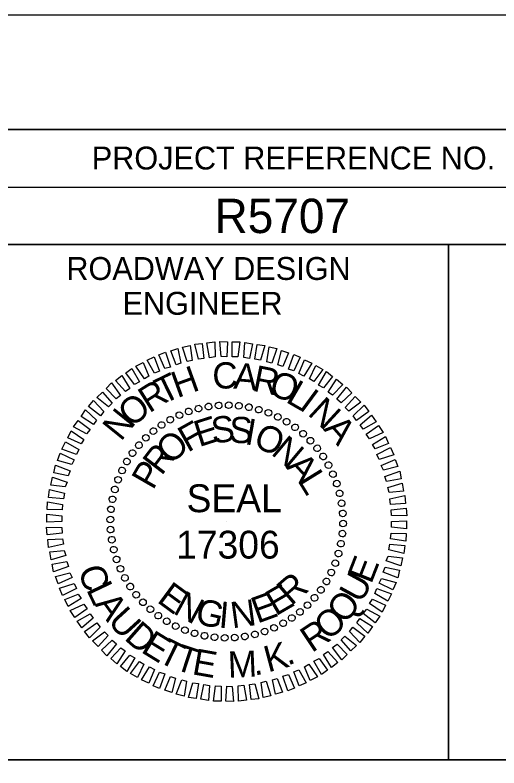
# Model space of a CAD drawing. Extents: x 573058.4 to 573116.8, y -55221.3 to -55199.3.
# Drawn here: x 573107.622 to 573109.734, y -55202.584 to -55199.298 of the extents above; entities that cross this region are included whole.
import ezdxf

# ---------------------------------------------------------------- set-up
doc = ezdxf.new("R2010")
doc.units = 0
for name, color, linetype in [('Prop Dimension', 7, 'Continuous'), ('Scratch_Level_1', 7, 'Continuous'), ('Sheet Data Field CELL', 7, 'Continuous'), ('Sheet Plot Border Inside CELL', 7, 'Continuous'), ('Sheet Profile CELL', 7, 'Continuous'), ('Sheet Sticker Exception Certification CELL', 7, 'Continuous')]:
    doc.layers.add(name, color=color, linetype=linetype)

msp = doc.modelspace()

# ---------------------------------------------------------------- linework, layer by layer
at = {"layer": 'Prop Dimension'}
for p, q in [((573108.4225, -55201.0155), (573108.4225, -55201.0155)), ((573108.467, -55201.0074), (573108.467, -55201.0074)), ((573108.5105, -55201.0013), (573108.5105, -55201.0013)), ((573108.555, -55201.0004), (573108.555, -55201.0004)), ((573108.5996, -55201.0034), (573108.5996, -55201.0034)), ((573108.6432, -55201.0106), (573108.6432, -55201.0106)), ((573108.6857, -55201.0196), (573108.6857, -55201.0196)), ((573108.3395, -55201.0439), (573108.3395, -55201.0439)), ((573108.38, -55201.0277), (573108.38, -55201.0277)), ((573108.7283, -55201.0337), (573108.7283, -55201.0337)), ((573108.7688, -55201.052), (573108.7688, -55201.052)), ((573108.2614, -55201.0875), (573108.2614, -55201.0875)), ((573108.2999, -55201.0641), (573108.2999, -55201.0641)), ((573108.8081, -55201.0722), (573108.8081, -55201.0722)), ((573108.2261, -55201.1127), (573108.2261, -55201.1127)), ((573108.8446, -55201.0976), (573108.8446, -55201.0976)), ((573108.8801, -55201.1249), (573108.8801, -55201.1249)), ((573108.1925, -55201.1431), (573108.1925, -55201.1431)), ((573108.9114, -55201.1552), (573108.9114, -55201.1552)), ((573108.1622, -55201.1746), (573108.1622, -55201.1746)), ((573108.9418, -55201.1888), (573108.9418, -55201.1888)), ((573108.1349, -55201.2099), (573108.1349, -55201.2099)), ((573108.1095, -55201.2464), (573108.1095, -55201.2464)), ((573108.9672, -55201.2241), (573108.9672, -55201.2241)), ((573108.0893, -55201.286), (573108.0893, -55201.286)), ((573108.9904, -55201.2626), (573108.9904, -55201.2626)), ((573109.0106, -55201.3022), (573109.0106, -55201.3022)), ((573108.071, -55201.3265), (573108.071, -55201.3265)), ((573109.0268, -55201.3427), (573109.0268, -55201.3427)), ((573108.0569, -55201.369), (573108.0569, -55201.369)), ((573109.039, -55201.3852), (573109.039, -55201.3852)), ((573108.0479, -55201.4115), (573108.0479, -55201.4115)), ((573109.0471, -55201.4297), (573109.0471, -55201.4297)), ((573108.0407, -55201.4549), (573108.0407, -55201.4549)), ((573109.0532, -55201.4732), (573109.0532, -55201.4732)), ((573108.0377, -55201.4995), (573108.0377, -55201.4995)), ((573108.546, -55201.5087), (573108.546, -55201.5087)), ((573109.0543, -55201.5177), (573109.0543, -55201.5177)), ((573108.0386, -55201.544), (573108.0386, -55201.544)), ((573109.0511, -55201.5623), (573109.0511, -55201.5623)), ((573108.0447, -55201.5877), (573108.0447, -55201.5877)), ((573109.0442, -55201.6059), (573109.0442, -55201.6059)), ((573108.0528, -55201.6322), (573108.0528, -55201.6322)), ((573109.0349, -55201.6484), (573109.0349, -55201.6484)), ((573108.065, -55201.6748), (573108.065, -55201.6748)), ((573108.0812, -55201.7153), (573108.0812, -55201.7153)), ((573109.0208, -55201.691), (573109.0208, -55201.691)), ((573109.0025, -55201.7315), (573109.0025, -55201.7315)), ((573108.1014, -55201.7546), (573108.1014, -55201.7546)), ((573108.9823, -55201.7708), (573108.9823, -55201.7708)), ((573108.1248, -55201.7931), (573108.1248, -55201.7931)), ((573108.9571, -55201.8073), (573108.9571, -55201.8073)), ((573108.15, -55201.8287), (573108.15, -55201.8287)), ((573108.9296, -55201.8428), (573108.9296, -55201.8428)), ((573108.1804, -55201.862), (573108.1804, -55201.862)), ((573108.8993, -55201.8741), (573108.8993, -55201.8741)), ((573108.2119, -55201.8923), (573108.2119, -55201.8923)), ((573108.866, -55201.9045), (573108.866, -55201.9045)), ((573108.2472, -55201.9198), (573108.2472, -55201.9198)), ((573108.2837, -55201.945), (573108.2837, -55201.945)), ((573108.8304, -55201.9299), (573108.8304, -55201.9299)), ((573108.3233, -55201.9652), (573108.3233, -55201.9652)), ((573108.7526, -55201.9733), (573108.7526, -55201.9733)), ((573108.7919, -55201.9531), (573108.7919, -55201.9531)), ((573108.3638, -55201.9835), (573108.3638, -55201.9835)), ((573108.4063, -55201.9976), (573108.4063, -55201.9976)), ((573108.4488, -55202.0069), (573108.4488, -55202.0069)), ((573108.625, -55202.0098), (573108.625, -55202.0098)), ((573108.6695, -55202.0017), (573108.6695, -55202.0017)), ((573108.7121, -55201.9895), (573108.7121, -55201.9895)), ((573108.4922, -55202.0138), (573108.4922, -55202.0138)), ((573108.5368, -55202.017), (573108.5368, -55202.017)), ((573108.5813, -55202.0159), (573108.5813, -55202.0159))]:
    msp.add_line(p, q, dxfattribs=at)
for points in [[(573108.4711, -55200.7939), (573108.4598, -55200.7291), (573108.4943, -55200.725), (573108.4954, -55200.7907)], [(573108.5217, -55200.7887), (573108.5165, -55200.723), (573108.5501, -55200.7239), (573108.546, -55200.7898)], [(573108.5703, -55200.7898), (573108.5703, -55200.7239), (573108.6036, -55200.725), (573108.5946, -55200.7907)], [(573108.6209, -55200.7928), (573108.625, -55200.7271), (573108.6583, -55200.7331), (573108.6452, -55200.7968)], [(573108.3253, -55200.8243), (573108.3019, -55200.7635), (573108.3334, -55200.7543), (573108.3464, -55200.8171)], [(573108.3739, -55200.811), (573108.3525, -55200.7473), (573108.3869, -55200.7401), (573108.395, -55200.806)], [(573108.4225, -55200.8), (573108.4063, -55200.7352), (573108.4396, -55200.732), (573108.4468, -55200.7968)], [(573108.6695, -55200.8009), (573108.6785, -55200.7361), (573108.7121, -55200.7412), (573108.6938, -55200.804)], [(573108.7211, -55200.8121), (573108.7312, -55200.7462), (573108.7656, -55200.7543), (573108.7424, -55200.8171)], [(573108.7697, -55200.8252), (573108.785, -55200.7624), (573108.8162, -55200.7725), (573108.791, -55200.8324)], [(573108.231, -55200.8616), (573108.1986, -55200.8049), (573108.2301, -55200.7907), (573108.2533, -55200.8526)], [(573108.2756, -55200.8405), (573108.2492, -55200.7817), (573108.2796, -55200.7696), (573108.301, -55200.8344)], [(573108.8153, -55200.8434), (573108.8385, -55200.7797), (573108.8669, -55200.7919), (573108.8385, -55200.8506)], [(573108.1876, -55200.8859), (573108.15, -55200.8312), (573108.1815, -55200.815), (573108.2067, -55200.8738)], [(573108.8608, -55200.8627), (573108.8862, -55200.8029), (573108.9175, -55200.8171), (573108.8831, -55200.8738)], [(573108.9074, -55200.8859), (573108.9348, -55200.8283), (573108.9652, -55200.8454), (573108.9267, -55200.8981)], [(573108.143, -55200.9113), (573108.1055, -55200.8596), (573108.1318, -55200.8405), (573108.1653, -55200.8992)], [(573108.947, -55200.9134), (573108.9823, -55200.8546), (573109.0086, -55200.8758), (573108.9692, -55200.9255)], [(573108.1046, -55200.9417), (573108.0609, -55200.8931), (573108.0884, -55200.8717), (573108.1237, -55200.9284)], [(573108.9884, -55200.9437), (573109.0259, -55200.8879), (573109.0523, -55200.9102), (573109.0077, -55200.9579)], [(573108.0641, -55200.973), (573108.0195, -55200.9284), (573108.0438, -55200.9041), (573108.0832, -55200.9588)], [(573109.0268, -55200.975), (573109.0685, -55200.9224), (573109.0928, -55200.9467), (573109.0462, -55200.9903)], [(573108.0305, -55201.0085), (573107.979, -55200.9669), (573108.0042, -55200.9437), (573108.0467, -55200.9923)], [(573107.9952, -55201.047), (573107.9426, -55201.0074), (573107.9648, -55200.9811), (573108.0094, -55201.0288)], [(573109.0633, -55201.0106), (573109.1069, -55200.9629), (573109.1312, -55200.9872), (573109.0786, -55201.0268)], [(573107.9648, -55201.0855), (573107.9102, -55201.0511), (573107.9293, -55201.0216), (573107.9779, -55201.0661)], [(573109.0988, -55201.047), (573109.1454, -55201.0013), (573109.1666, -55201.0288), (573109.113, -55201.0673)], [(573109.1292, -55201.0864), (573109.1787, -55201.0439), (573109.1981, -55201.0733), (573109.1414, -55201.1057)], [(573107.9345, -55201.126), (573107.8778, -55201.0956), (573107.898, -55201.0673), (573107.9507, -55201.1078)], [(573109.1555, -55201.128), (573109.2091, -55201.0895), (573109.2284, -55201.1199), (573109.1697, -55201.1483)], [(573107.9102, -55201.1694), (573107.8523, -55201.1442), (573107.8676, -55201.1127), (573107.9223, -55201.1503)], [(573109.1819, -55201.1726), (573109.2386, -55201.137), (573109.2516, -55201.1685), (573109.194, -55201.1917)], [(573107.8899, -55201.216), (573107.8271, -55201.1928), (573107.8422, -55201.1613), (573107.9, -55201.1937)], [(573109.2021, -55201.216), (573109.2617, -55201.1856), (573109.275, -55201.218), (573109.2122, -55201.2383)], [(573107.8697, -55201.2605), (573107.8069, -55201.2423), (573107.8199, -55201.211), (573107.8807, -55201.2394)], [(573109.2203, -55201.2637), (573109.282, -55201.2374), (573109.2932, -55201.2686), (573109.2305, -55201.2848)], [(573107.8544, -55201.3091), (573107.7916, -55201.2961), (573107.7988, -55201.2626), (573107.8625, -55201.288)], [(573109.2365, -55201.3123), (573109.3013, -55201.2889), (573109.3074, -55201.3224), (573109.2435, -55201.3334)], [(573107.8413, -55201.3577), (573107.7785, -55201.3496), (573107.7855, -55201.3152), (573107.8494, -55201.3366)], [(573109.2487, -55201.3609), (573109.3124, -55201.3415), (573109.3184, -55201.376), (573109.2548, -55201.382)], [(573107.8332, -55201.4095), (573107.7684, -55201.4034), (573107.7725, -55201.369), (573107.8382, -55201.3852)], [(573109.2577, -55201.4095), (573109.3236, -55201.3953), (573109.3265, -55201.4297), (573109.2617, -55201.4338)], [(573107.828, -55201.4581), (573107.7623, -55201.4561), (573107.7644, -55201.4225), (573107.8301, -55201.4338)], [(573109.2638, -55201.4581), (573109.3297, -55201.45), (573109.3317, -55201.4844), (573109.2658, -55201.4824)], [(573107.8271, -55201.5087), (573107.7612, -55201.5116), (573107.7612, -55201.4772), (573107.8271, -55201.4844)], [(573109.2649, -55201.5087), (573109.3306, -55201.5056), (573109.3306, -55201.54), (573109.2649, -55201.533)], [(573107.828, -55201.5593), (573107.7623, -55201.5674), (573107.7603, -55201.533), (573107.826, -55201.535)], [(573107.8341, -55201.6079), (573107.7684, -55201.6221), (573107.7653, -55201.5877), (573107.8301, -55201.5836)], [(573109.2638, -55201.5593), (573109.3297, -55201.5614), (573109.3277, -55201.5947), (573109.2617, -55201.5836)], [(573109.2588, -55201.6079), (573109.3236, -55201.614), (573109.3196, -55201.6484), (573109.2536, -55201.6322)], [(573107.8433, -55201.6565), (573107.7794, -55201.6757), (573107.7734, -55201.6412), (573107.8373, -55201.6352)], [(573109.2507, -55201.6595), (573109.3135, -55201.6676), (573109.3063, -55201.702), (573109.2426, -55201.6808)], [(573107.8555, -55201.7051), (573107.7907, -55201.7283), (573107.7846, -55201.695), (573107.8483, -55201.6838)], [(573109.2374, -55201.7081), (573109.3002, -55201.7213), (573109.2932, -55201.7546), (573109.2293, -55201.7294)], [(573107.8717, -55201.7537), (573107.8098, -55201.7801), (573107.7988, -55201.7486), (573107.8616, -55201.7324)], [(573107.8899, -55201.8012), (573107.8301, -55201.8316), (573107.817, -55201.7992), (573107.8798, -55201.7789)], [(573109.2224, -55201.7567), (573109.2851, -55201.7749), (573109.2719, -55201.8064), (573109.2111, -55201.778)], [(573109.2021, -55201.8012), (573109.2649, -55201.8246), (573109.2496, -55201.8559), (573109.192, -55201.8235)], [(573107.9102, -55201.8449), (573107.8535, -55201.8802), (573107.8402, -55201.8489), (573107.898, -55201.8255)], [(573109.1819, -55201.8478), (573109.2395, -55201.8732), (573109.2244, -55201.9045), (573109.1697, -55201.8671)], [(573107.9365, -55201.8894), (573107.8827, -55201.9279), (573107.8636, -55201.8975), (573107.9223, -55201.8692)], [(573107.9628, -55201.9308), (573107.9131, -55201.9733), (573107.894, -55201.9441), (573107.9507, -55201.9117)], [(573109.1576, -55201.8914), (573109.2143, -55201.9218), (573109.194, -55201.9502), (573109.1414, -55201.9097)], [(573109.1272, -55201.9319), (573109.1819, -55201.9664), (573109.1625, -55201.9956), (573109.1139, -55201.9511)], [(573107.9932, -55201.9704), (573107.9466, -55202.0159), (573107.9252, -55201.9886), (573107.979, -55201.9502)], [(573109.0968, -55201.9704), (573109.1495, -55202.0098), (573109.1272, -55202.0361), (573109.0826, -55201.9886)], [(573108.0285, -55202.0069), (573107.9851, -55202.0543), (573107.9608, -55202.03), (573108.0134, -55201.9907)], [(573109.0613, -55202.0089), (573109.113, -55202.0503), (573109.0876, -55202.0737), (573109.0451, -55202.0251)], [(573108.065, -55202.0422), (573108.0236, -55202.0948), (573107.9993, -55202.0705), (573108.0458, -55202.0271)], [(573109.028, -55202.0442), (573109.0725, -55202.0888), (573109.0482, -55202.1131), (573109.0086, -55202.0584)], [(573108.1034, -55202.0737), (573108.0661, -55202.1293), (573108.0398, -55202.107), (573108.0843, -55202.0595)], [(573108.9875, -55202.0757), (573109.0309, -55202.1243), (573109.0037, -55202.1455), (573108.9681, -55202.0888)], [(573108.1451, -55202.1041), (573108.1095, -55202.1628), (573108.0832, -55202.1414), (573108.1228, -55202.0919)], [(573108.949, -55202.1061), (573108.9863, -55202.1576), (573108.96, -55202.177), (573108.9267, -55202.1182)], [(573108.1844, -55202.1313), (573108.1572, -55202.1891), (573108.1268, -55202.1718), (573108.1653, -55202.1191)], [(573108.231, -55202.1547), (573108.2058, -55202.2143), (573108.1743, -55202.2001), (573108.2087, -55202.1434)], [(573108.9044, -55202.1313), (573108.9418, -55202.186), (573108.9105, -55202.2022), (573108.8851, -55202.1434)], [(573108.2767, -55202.1738), (573108.2533, -55202.2377), (573108.2249, -55202.2256), (573108.2533, -55202.1668)], [(573108.8608, -55202.1556), (573108.8932, -55202.2123), (573108.8619, -55202.2265), (573108.8385, -55202.1648)], [(573108.3221, -55202.192), (573108.3071, -55202.2548), (573108.2756, -55202.2447), (573108.301, -55202.1851)], [(573108.3707, -55202.2053), (573108.3606, -55202.271), (573108.3262, -55202.2629), (573108.3496, -55202.2001)], [(573108.7181, -55202.2062), (573108.7393, -55202.2701), (573108.7049, -55202.2771), (573108.6968, -55202.2114)], [(573108.7667, -55202.1932), (573108.7899, -55202.2539), (573108.7586, -55202.2629), (573108.7454, -55202.2001)], [(573108.8162, -55202.177), (573108.8426, -55202.2357), (573108.8122, -55202.2478), (573108.791, -55202.183)], [(573108.4225, -55202.2163), (573108.4133, -55202.2811), (573108.38, -55202.2762), (573108.3982, -55202.2134)], [(573108.4711, -55202.2244), (573108.467, -55202.2904), (573108.4335, -55202.2843), (573108.4468, -55202.2204)], [(573108.5217, -55202.2276), (573108.5217, -55202.2933), (573108.4882, -55202.2924), (573108.4974, -55202.2265)], [(573108.5703, -55202.2285), (573108.5753, -55202.2944), (573108.542, -55202.2933), (573108.546, -55202.2276)], [(573108.6209, -55202.2235), (573108.632, -55202.2883), (573108.5975, -55202.2924), (573108.5966, -55202.2265)], [(573108.6695, -55202.2175), (573108.6857, -55202.2823), (573108.6522, -55202.2852), (573108.6452, -55202.2204)]]:
    msp.add_lwpolyline(points, close=True, dxfattribs=at)
for centre, major_axis in [((573108.4666, -55201.007), (-0.0023, 0.0144)), ((573108.5106, -55201.002), (-0.001, 0.0145)), ((573108.5549, -55201.0009), (0.0003, 0.0146)), ((573108.5991, -55201.0036), (0.0015, 0.0145)), ((573108.3807, -55201.0284), (-0.0047, 0.0138)), ((573108.4232, -55201.0159), (-0.0035, 0.0141)), ((573108.6429, -55201.0101), (0.0028, 0.0143)), ((573108.686, -55201.0205), (0.004, 0.014)), ((573108.728, -55201.0345), (0.0052, 0.0136)), ((573108.2998, -55201.0645), (-0.0071, 0.0128)), ((573108.3394, -55201.0447), (-0.0059, 0.0133)), ((573108.7687, -55201.0522), (0.0064, 0.0131)), ((573108.8076, -55201.0733), (0.0075, 0.0125)), ((573108.262, -55201.0876), (-0.0082, 0.0121)), ((573108.8445, -55201.0978), (0.0086, 0.0118)), ((573108.2264, -55201.114), (-0.0092, 0.0113)), ((573108.8792, -55201.1254), (0.0096, 0.011)), ((573108.1932, -55201.1433), (-0.0101, 0.0105)), ((573108.9113, -55201.1559), (0.0105, 0.0101)), ((573108.1627, -55201.1755), (-0.011, 0.0096)), ((573108.9407, -55201.189), (0.0113, 0.0092)), ((573108.1351, -55201.2101), (-0.0118, 0.0086)), ((573108.9671, -55201.2246), (0.0121, 0.0082)), ((573108.1107, -55201.2471), (-0.0125, 0.0075)), ((573108.9902, -55201.2624), (0.0128, 0.0071)), ((573108.0895, -55201.286), (-0.0131, 0.0064)), ((573109.01, -55201.3021), (0.0133, 0.0059)), ((573108.0719, -55201.3266), (-0.0136, 0.0052)), ((573108.0578, -55201.3687), (-0.014, 0.004)), ((573109.0262, -55201.3433), (0.0138, 0.0047)), ((573109.0388, -55201.3858), (0.0141, 0.0035)), ((573108.0475, -55201.4117), (-0.0143, 0.0028)), ((573109.0476, -55201.4292), (0.0144, 0.0023)), ((573108.0409, -55201.4556), (-0.0145, 0.0015)), ((573108.0382, -55201.4998), (-0.0146, 0.0003)), ((573109.0527, -55201.4732), (0.0145, 0.001)), ((573109.0538, -55201.5175), (0.0146, -0.0003)), ((573108.0394, -55201.5441), (-0.0145, -0.001)), ((573109.0511, -55201.5617), (0.0145, -0.0015)), ((573108.0444, -55201.5881), (-0.0144, -0.0023)), ((573108.0532, -55201.6315), (-0.0141, -0.0035)), ((573109.0446, -55201.6056), (0.0143, -0.0028)), ((573109.0342, -55201.6486), (0.014, -0.004)), ((573108.0658, -55201.674), (-0.0138, -0.0047)), ((573109.0202, -55201.6907), (0.0136, -0.0052)), ((573108.0821, -55201.7152), (-0.0133, -0.0059)), ((573109.0025, -55201.7313), (0.0131, -0.0064)), ((573108.1018, -55201.7549), (-0.0128, -0.0071)), ((573108.125, -55201.7926), (-0.0121, -0.0082)), ((573108.9813, -55201.7702), (0.0125, -0.0075)), ((573108.1513, -55201.8283), (-0.0113, -0.0092)), ((573108.9569, -55201.8072), (0.0118, -0.0086)), ((573108.1807, -55201.8614), (-0.0105, -0.0101)), ((573108.9293, -55201.8418), (0.011, -0.0096)), ((573108.2128, -55201.8919), (-0.0096, -0.011)), ((573108.8988, -55201.874), (0.0101, -0.0105)), ((573108.2475, -55201.9195), (-0.0086, -0.0118)), ((573108.83, -55201.9297), (0.0082, -0.0121)), ((573108.8656, -55201.9033), (0.0092, -0.0113)), ((573108.2844, -55201.944), (-0.0075, -0.0125)), ((573108.7922, -55201.9528), (0.0071, -0.0128)), ((573108.3234, -55201.9651), (-0.0064, -0.0131)), ((573108.364, -55201.9828), (-0.0052, -0.0136)), ((573108.7114, -55201.9888), (0.0047, -0.0138)), ((573108.7526, -55201.9726), (0.0059, -0.0133)), ((573108.406, -55201.9968), (-0.004, -0.014)), ((573108.4491, -55202.0072), (-0.0028, -0.0143)), ((573108.4929, -55202.0137), (-0.0015, -0.0145)), ((573108.5372, -55202.0164), (-0.0003, -0.0146)), ((573108.5814, -55202.0153), (0.001, -0.0145)), ((573108.6255, -55202.0103), (0.0023, -0.0144)), ((573108.6689, -55202.0014), (0.0035, -0.0141))]:
    msp.add_ellipse(centre, major_axis=major_axis, ratio=0.999708, dxfattribs=at)
at = {"layer": 'Scratch_Level_1'}
msp.add_line((573108.546, -55201.5087), (573108.546, -55201.5087), dxfattribs=at)
at = {"layer": 'Sheet Plot Border Inside CELL'}
msp.add_lwpolyline([(573112.0142, -55199.2984), (573078.0142, -55199.2984), (573078.0142, -55221.2984), (573112.0142, -55221.2984)], close=True, dxfattribs=at)
at = {"layer": 'Sheet Profile CELL'}
for p, q in [((573107.5142, -55200.0494), (573111.5142, -55200.0494)), ((573109.5142, -55200.2994), (573109.5142, -55202.5484))]:
    msp.add_line(p, q, dxfattribs=at)
for points in [[(573111.5142, -55199.7984), (573081.5142, -55199.7984), (573081.5142, -55220.7984), (573111.5142, -55220.7984)], [(573107.5142, -55199.7984), (573111.5142, -55199.7984), (573111.5142, -55200.2994), (573107.5142, -55200.2994)], [(573107.5142, -55200.2994), (573109.5142, -55200.2994), (573109.5142, -55202.5494), (573107.5142, -55202.5494)], [(573109.5142, -55200.2994), (573111.5142, -55200.2994), (573111.5142, -55202.5494), (573109.5142, -55202.5494)]]:
    msp.add_lwpolyline(points, close=True, dxfattribs=at)
at = {"layer": 'Sheet Sticker Exception Certification CELL'}
msp.add_line((573107.5142, -55202.5494), (573111.5149, -55202.5494), dxfattribs=at)

# ---------------------------------------------------------------- texts
at = {"layer": 'Prop Dimension'}
for s, height, rotation, p in [('C', 0.1144, 1.0718, (573108.4844, -55200.9293)), ('A', 0.1144, 354.8222, (573108.5735, -55200.9282)), ('R', 0.1144, 348.5725, (573108.6545, -55200.9374)), ('T', 0.1144, 26.0703, (573108.2688, -55200.9991)), ('H', 0.1144, 19.8207, (573108.3305, -55200.9707)), ('O', 0.1144, 342.3229, (573108.7253, -55200.9557)), ('L', 0.1144, 329.8237, (573108.7994, -55200.9849)), ('R', 0.1144, 32.3199, (573108.2081, -55201.0376)), ('O', 0.1144, 38.5695, (573108.13, -55201.1015)), ('I', 0.1144, 323.5741, (573108.8561, -55201.0144)), ('N', 0.1144, 317.3244, (573108.8954, -55201.0407)), ('N', 0.1144, 51.0688, (573108.0845, -55201.1622)), ('E', 0.1144, 17.6709, (573108.4256, -55201.1845)), ('S', 0.1144, 6.1833, (573108.4844, -55201.1683)), ('S', 0.1144, 358.4778, (573108.5564, -55201.1651)), ('F', 0.1144, 29.3, (573108.3761, -55201.2088)), ('I', 0.1144, 350.0931, (573108.6212, -55201.1703)), ('O', 0.1144, 335.3611, (573108.6565, -55201.1773)), ('A', 0.1144, 311.0748, (573108.9654, -55201.1064)), ('O', 0.1144, 43.5875, (573108.3041, -55201.2635)), ('N', 0.1144, 319.95, (573108.7355, -55201.2128)), ('R', 0.1144, 52.4166, (573108.2616, -55201.3121)), ('P', 0.1144, 60.1222, (573108.2243, -55201.3748)), ('A', 0.1144, 312.2445, (573108.8023, -55201.2725)), ('L', 0.1144, 301.6752, (573108.8529, -55201.3292)), ('SEAL', 0.1215, 0, (573108.371, -55201.468)), ('17306', 0.1215, 0, (573108.3255, -55201.6705)), ('E', 0.1144, 68.6635, (573109.1769, -55201.7848)), ('C', 0.1144, 287.4003, (573107.8971, -55201.718)), ('R', 0.1144, 40.7353, (573108.8277, -55201.8791)), ('U', 0.1144, 61.3078, (573109.1324, -55201.8698)), ('L', 0.1144, 295.5141, (573107.9315, -55201.805)), ('E', 0.1144, 323.6798, (573108.2373, -55201.8577)), ('E', 0.1144, 30.1214, (573108.7598, -55201.9236)), ('N', 0.1144, 331.3854, (573108.3073, -55201.9074)), ('A', 0.1144, 306.1492, (573107.9671, -55201.8698)), ('G', 0.1144, 346.7965, (573108.4034, -55201.952)), ('E', 0.1144, 20.0411, (573108.6799, -55201.9549)), ('Q', 0.1144, 52.3928, (573109.0646, -55201.9601)), ('U', 0.1144, 312.3988, (573108.0227, -55201.9468)), ('I', 0.1144, 355.0405, (573108.5087, -55201.9711)), ('N', 0.1144, 7.7341, (573108.5705, -55201.9751)), ('O', 0.1144, 39.8936, (573108.9877, -55202.0318)), ('D', 0.1144, 318.6484, (573108.0947, -55202.0208)), ('R', 0.1144, 33.6439, (573108.9177, -55202.0836)), ('E', 0.1144, 328.3523, (573108.1676, -55202.0764)), ('T', 0.1144, 333.6523, (573108.2393, -55202.1169)), ('T', 0.1144, 341.812, (573108.3122, -55202.1513)), ('K', 0.1144, 14.8951, (573108.7265, -55202.1675)), ('E', 0.1144, 349.8966, (573108.3912, -55202.1747)), ('M', 0.1144, 2.3958, (573108.5532, -55202.1909)), ('.', 0.1144, 21.1447, (573108.8124, -55202.1383)), ('.', 0.1144, 8.6454, (573108.6666, -55202.1808))]:
    msp.add_text(s, height=height, rotation=rotation, dxfattribs=at).set_placement(p)
at = {"layer": 'Sheet Data Field CELL'}
msp.add_text('R5707', height=0.15, dxfattribs=at).set_placement((573108.493, -55200.2499))
at = {"layer": 'Sheet Profile CELL'}
for s, height, p in [('PROJECT REFERENCE NO.', 0.100002, (573107.9572, -55199.9724)), ('ROADWAY DESIGN', 0.100002, (573107.8462, -55200.4544)), ('ENGINEER', 0.1, (573108.0912, -55200.6064))]:
    msp.add_text(s, height=height, dxfattribs=at).set_placement(p)

doc.saveas('drawing.dxf')
